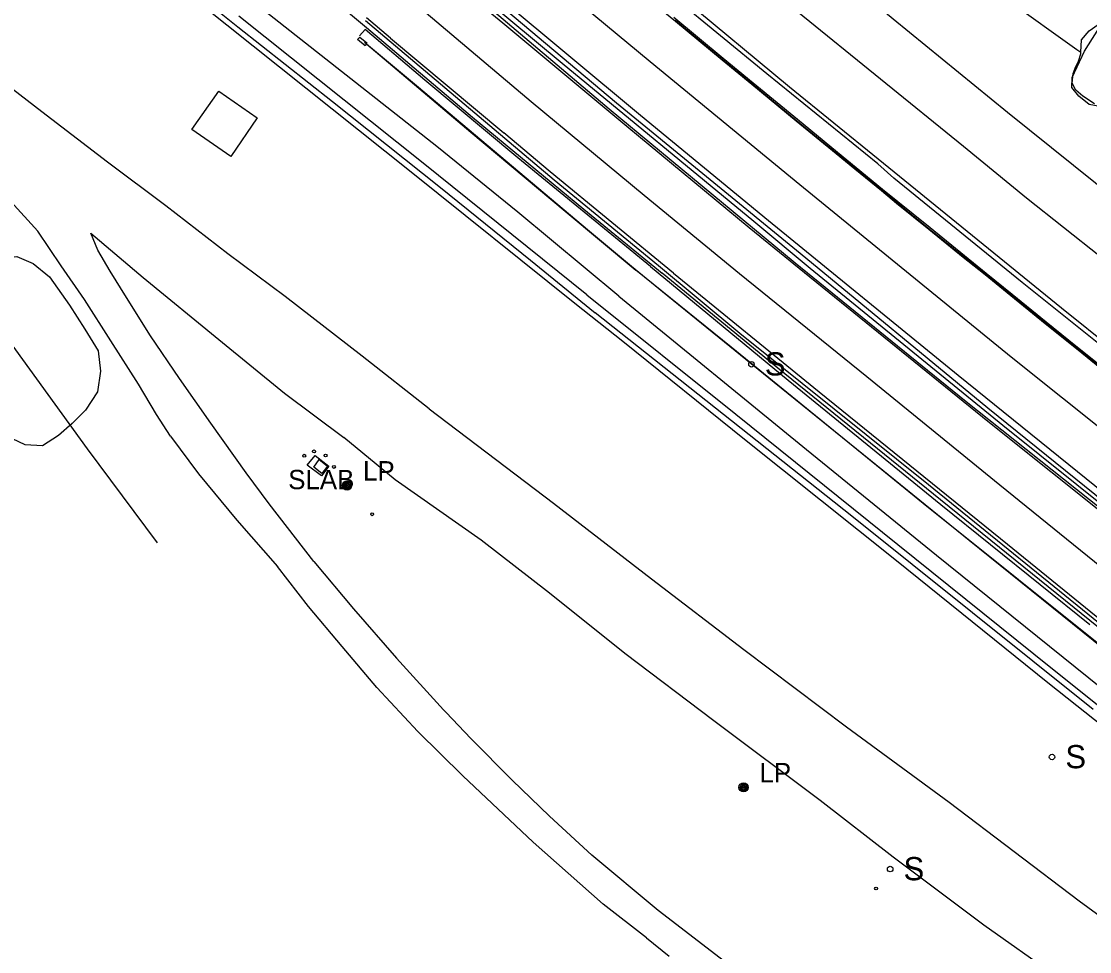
# Model space of a CAD drawing. Extents: x 368532 to 392481, y 10654822 to 10676899.
# Drawn here: x 379727.7 to 380004, y 10659071.4 to 10659311.8 of the extents above; entities that cross this region are included whole.
import ezdxf

# ---------------------------------------------------------------- set-up
doc = ezdxf.new("R2010")
doc.units = 0
for name, color, linetype in [('p_dtm obscured area', 7, 'Continuous'), ('p_dtm retaining wall', 7, 'Continuous'), ('p_dtm sidewalk', 7, 'Continuous'), ('p_dtm slab', 7, 'Continuous'), ('p_railroad rr control', 7, 'Continuous'), ('p_road - paved curb', 7, 'Continuous'), ('p_road conc barrier', 7, 'Continuous'), ('p_road dirt road', 7, 'Continuous'), ('p_road paint stripe', 7, 'Continuous'), ('p_structure building', 7, 'Continuous'), ('p_structure fence', 7, 'Continuous'), ('p_structure sign', 7, 'Continuous'), ('p_structure unidentified', 7, 'Continuous'), ('p_structure wall', 7, 'Continuous'), ('p_utility general pole', 7, 'Continuous'), ('p_veg woods', 7, 'Continuous')]:
    doc.layers.add(name, color=color, linetype=linetype)

msp = doc.modelspace()

# ---------------------------------------------------------------- linework, layer by layer
at = {"layer": 'p_dtm obscured area'}
msp.add_lwpolyline([(380005.29, 10659290.55), (380002.2, 10659292.5), (380000.46, 10659294.07), (379999.46, 10659295.89), (379999.7, 10659298.41), (380000.25, 10659299.73), (380001.13, 10659301.52), (380001.73, 10659303.48), (380001.72, 10659303.82), (380001.72, 10659303.89), (380001.89, 10659307.03), (380003.9, 10659309.42), (380006.21, 10659311)], dxfattribs=at)
at = {"layer": 'p_dtm retaining wall'}
for p, q in [((379982.87, 10659317.34), (380000.72, 10659304.61)), ((379816.5, 10659306.51), (379830.44, 10659294.8)), ((380000.72, 10659304.61), (380001.72, 10659303.89)), ((379830.44, 10659294.8), (379851.18, 10659277.37)), ((379851.18, 10659277.37), (379874.69, 10659257.62)), ((379874.69, 10659257.62), (379885.52, 10659248.52)), ((379885.52, 10659248.52), (379893.51, 10659242.05)), ((379893.51, 10659242.05), (379922.46, 10659218.6)), ((379922.46, 10659218.6), (379947.37, 10659198.43)), ((379947.37, 10659198.43), (379972.88, 10659177.76)), ((379972.88, 10659177.76), (380010.92, 10659146.96))]:
    msp.add_line(p, q, dxfattribs=at)
at = {"layer": 'p_dtm sidewalk'}
for p, q in [((379920.51, 10659298.28), (379890.66, 10659322.93)), ((379816.67, 10659309.76), (379815.2, 10659308.07)), ((379832.07, 10659296.67), (379816.67, 10659309.76)), ((379949.2, 10659274.99), (379920.51, 10659298.28)), ((379856.11, 10659276.58), (379832.07, 10659296.67)), ((379890.4, 10659248.47), (379856.11, 10659276.58)), ((379953.34, 10659271.29), (379949.2, 10659274.99)), ((379986.54, 10659244.35), (379953.34, 10659271.29)), ((379890.4, 10659248.47), (379926, 10659219.11)), ((380020.43, 10659217.2), (379986.54, 10659244.35)), ((379926, 10659219.11), (379965.55, 10659186.98)), ((379965.55, 10659186.98), (380004.03, 10659155.88))]:
    msp.add_line(p, q, dxfattribs=at)
at = {"layer": 'p_dtm slab'}
for p, q in [((379801.61, 10659197.14), (379803.71, 10659199.65)), ((379803.71, 10659199.65), (379807.29, 10659196.89)), ((379805.36, 10659194.34), (379801.61, 10659197.14)), ((379807.29, 10659196.89), (379805.36, 10659194.34))]:
    msp.add_line(p, q, dxfattribs=at)
at = {"layer": 'p_railroad rr control'}
for points in [[(379569.61, 10659644.13), (379609.83, 10659608.08), (379650.67, 10659571.51), (379694.41, 10659532.52), (379741.58, 10659490.92), (379776.45, 10659460.68), (379817.46, 10659425.32), (379860.06, 10659389.56), (379903.79, 10659353.23), (379953.19, 10659312.49), (379982.8, 10659288.36)], [(379971.34, 10659279.52), (379928.46, 10659314.3), (379890.23, 10659345.82), (379857.28, 10659373.19), (379831.54, 10659394.75), (379804.64, 10659417.62), (379771.87, 10659445.91), (379742.98, 10659470.6), (379703.31, 10659505.21), (379666.94, 10659537.5), (379639.55, 10659561.66), (379602.83, 10659594.67), (379578.33, 10659616.76), (379559.4, 10659633.6)], [(379982.8, 10659288.36), (380016.9, 10659261), (380052.84, 10659232.61), (380085.94, 10659206.26), (380120.72, 10659179.3), (380153.32, 10659154.27), (380191.45, 10659125.29), (380231.37, 10659095.21), (380261.57, 10659072.75), (380294.45, 10659048.57), (380330.85, 10659022.17), (380360.99, 10659000.26)], [(380347.38, 10658976.44), (380320.5, 10658997.04), (380307.32, 10659007.82), (380293.12, 10659020.18), (380275.57, 10659035.91), (380257.07, 10659052.87), (380239.39, 10659068.32), (380225.36, 10659080.48), (380211.07, 10659092.38), (380190.43, 10659108.38), (380160.49, 10659131.03), (380132.22, 10659152.81), (380112.56, 10659167.73), (380088.41, 10659186.61), (380066.31, 10659204.03), (380047.58, 10659218.72), (380026.77, 10659235.12), (380006.83, 10659250.97), (379987.69, 10659266.12), (379971.34, 10659279.52)]]:
    msp.add_lwpolyline(points, dxfattribs=at)
at = {"layer": 'p_road - paved curb'}
for p, q in [((379828.13, 10659335.86), (379881.64, 10659290.75)), ((379879.79, 10659289.19), (379832.82, 10659328.91)), ((379816.7, 10659312.04), (379865.52, 10659270.84)), ((379909.27, 10659302.21), (379896.43, 10659312.84)), ((379909.05, 10659301.94), (379896.78, 10659312.1)), ((379916.76, 10659295.62), (379909.05, 10659301.94)), ((379916.98, 10659295.89), (379909.27, 10659302.21)), ((379928.2, 10659286.17), (379916.76, 10659295.62)), ((379928.42, 10659286.44), (379916.98, 10659295.89)), ((379881.64, 10659290.75), (379929.16, 10659251.92)), ((379927.87, 10659249.32), (379879.79, 10659289.19)), ((379938.56, 10659277.71), (379928.2, 10659286.17)), ((379938.78, 10659277.98), (379928.42, 10659286.44)), ((379943.37, 10659273.74), (379938.56, 10659277.71)), ((379943.59, 10659274.01), (379938.78, 10659277.98)), ((379950.23, 10659268.15), (379943.37, 10659273.74)), ((379950.46, 10659268.42), (379943.59, 10659274.01)), ((379865.52, 10659270.84), (379892.53, 10659248.76)), ((379954.18, 10659264.92), (379950.23, 10659268.15)), ((379954.41, 10659265.19), (379950.46, 10659268.42)), ((379962.53, 10659258.16), (379954.18, 10659264.92)), ((379962.75, 10659258.43), (379954.41, 10659265.19)), ((379971.41, 10659250.96), (379962.53, 10659258.16)), ((379971.63, 10659251.23), (379962.75, 10659258.43)), ((379929.16, 10659251.92), (379977.66, 10659211.92)), ((379977.04, 10659246.42), (379971.41, 10659250.96)), ((379977.27, 10659246.69), (379971.63, 10659251.23)), ((379892.53, 10659248.76), (379913.53, 10659231.25)), ((379971.64, 10659213.83), (379927.87, 10659249.32)), ((379983.7, 10659240.97), (379977.04, 10659246.42)), ((379983.93, 10659241.24), (379977.27, 10659246.69)), ((379992.58, 10659233.8), (379983.7, 10659240.97)), ((379992.8, 10659234.07), (379983.93, 10659241.24)), ((380000.9, 10659227.55), (379992.8, 10659234.07)), ((380000.68, 10659227.28), (379992.58, 10659233.8)), ((379913.53, 10659231.25), (379962.31, 10659192.11)), ((380010.89, 10659219.06), (380000.68, 10659227.28)), ((380011.11, 10659219.33), (380000.9, 10659227.55)), ((380023.61, 10659172.45), (379971.64, 10659213.83)), ((379977.66, 10659211.92), (380025.93, 10659173.01)), ((379962.31, 10659192.11), (380009.44, 10659153.87))]:
    msp.add_line(p, q, dxfattribs=at)
for points in [[(380000.59, 10659227.16), (379992.49, 10659233.68), (379983.61, 10659240.85), (379976.95, 10659246.3), (379971.32, 10659250.84), (379962.44, 10659258.04), (379954.09, 10659264.8), (379950.14, 10659268.03), (379943.27, 10659273.62), (379938.46, 10659277.59), (379928.1, 10659286.05), (379916.66, 10659295.5), (379908.95, 10659301.82), (379896.93, 10659311.78), (379896.93, 10659311.78), (379888.66, 10659318.64)], [(380173.31, 10659088.75), (380166.18, 10659094.46), (380158.38, 10659100.73), (380149.87, 10659107.54), (380139.52, 10659115.87), (380122.6, 10659129.43), (380116.16, 10659134.59), (380109.42, 10659140.03), (380104.58, 10659143.88), (380097.03, 10659149.96), (380092.19, 10659153.84), (380084.69, 10659159.83), (380077.34, 10659165.7), (380071.85, 10659170.15), (380064.49, 10659175.96), (380059.28, 10659180.18), (380053.58, 10659184.67), (380048.2, 10659188.95), (380042.38, 10659193.61), (380037.34, 10659197.65), (380026.17, 10659206.53), (380016.41, 10659214.49), (380010.8, 10659218.94), (380000.59, 10659227.16)]]:
    msp.add_lwpolyline(points, dxfattribs=at)
at = {"layer": 'p_road conc barrier'}
for p, q in [((379781.82, 10659339.53), (379817.01, 10659310.29)), ((379867.58, 10659300.98), (379827.67, 10659334.33)), ((379887.43, 10659327.32), (379926.4, 10659294.96)), ((379817.01, 10659310.29), (379844.41, 10659287.12)), ((379917.2, 10659260.08), (379867.58, 10659300.98)), ((379926.4, 10659294.96), (379949.33, 10659276.27)), ((379844.41, 10659287.12), (379873.18, 10659263.31)), ((379949.33, 10659276.27), (379996.75, 10659237.79)), ((379873.18, 10659263.31), (379893.44, 10659246.77)), ((379931.73, 10659247.97), (379917.2, 10659260.08)), ((379981.51, 10659207.38), (379931.73, 10659247.97)), ((379923.36, 10659222.19), (379893.44, 10659246.77)), ((379996.75, 10659237.79), (380043.04, 10659200.37)), ((379965.42, 10659188.13), (379923.36, 10659222.19)), ((380030.82, 10659167.77), (379981.51, 10659207.38)), ((380006.33, 10659155.19), (379965.42, 10659188.13))]:
    msp.add_line(p, q, dxfattribs=at)
at = {"layer": 'p_road dirt road'}
for p, q in [((379733.04, 10659288.45), (379717.81, 10659300.11)), ((379749.98, 10659275.48), (379733.04, 10659288.45)), ((379765.12, 10659264.18), (379749.98, 10659275.48)), ((379731.98, 10659257.6), (379724.99, 10659265.27)), ((379781.13, 10659251.71), (379765.12, 10659264.18)), ((379738.02, 10659248.66), (379731.98, 10659257.6)), ((379747.52, 10659252.72), (379745.69, 10659257.05)), ((379745.69, 10659257.05), (379759.2, 10659245.65)), ((379750.71, 10659247.27), (379747.52, 10659252.72)), ((379795.98, 10659240.76), (379781.13, 10659251.71)), ((379744.04, 10659239.94), (379738.02, 10659248.66)), ((379754.91, 10659240.48), (379750.71, 10659247.27)), ((379759.2, 10659245.65), (379778.84, 10659229.57)), ((379750.84, 10659229.27), (379744.04, 10659239.94)), ((379761.17, 10659230.51), (379754.91, 10659240.48)), ((379815.9, 10659225.26), (379795.98, 10659240.76)), ((379758, 10659218.06), (379750.84, 10659229.27)), ((379768.66, 10659219.56), (379761.17, 10659230.51)), ((379778.84, 10659229.57), (379795.79, 10659215.73)), ((379833.17, 10659211.68), (379815.9, 10659225.26)), ((379762.71, 10659210.21), (379758, 10659218.06)), ((379776.7, 10659207.95), (379768.66, 10659219.56)), ((379795.79, 10659215.73), (379811.14, 10659204.23)), ((379766.35, 10659204.6), (379762.71, 10659210.21)), ((379833.17, 10659211.68), (379865.37, 10659187.26)), ((379785.85, 10659195.17), (379776.7, 10659207.95)), ((379766.35, 10659204.6), (379773.51, 10659194.85)), ((379824.43, 10659193.35), (379811.14, 10659204.23)), ((379773.51, 10659194.85), (379783.43, 10659182.86)), ((379791.83, 10659187.16), (379785.85, 10659195.17)), ((379846.67, 10659177.73), (379824.43, 10659193.35)), ((379803.39, 10659172.2), (379791.83, 10659187.16)), ((379865.37, 10659187.26), (379890.68, 10659167.7)), ((379783.43, 10659182.86), (379793.96, 10659170.89)), ((379864.31, 10659164.02), (379846.67, 10659177.73)), ((379801.97, 10659160.57), (379793.96, 10659170.89)), ((379803.39, 10659172.2), (379813.65, 10659159.94)), ((379890.68, 10659167.7), (379914.55, 10659149.44)), ((379883.81, 10659148.39), (379864.31, 10659164.02)), ((379810.67, 10659150.24), (379801.97, 10659160.57)), ((379813.65, 10659159.94), (379824.75, 10659147.25)), ((379819.65, 10659139.61), (379810.67, 10659150.24)), ((379914.55, 10659149.44), (379941.15, 10659129.51)), ((379824.75, 10659147.25), (379836.93, 10659133.88)), ((379906.83, 10659131.06), (379883.81, 10659148.39)), ((379830.24, 10659128.3), (379819.65, 10659139.61)), ((379836.93, 10659133.88), (379837.59, 10659133.21)), ((379843.96, 10659126.43), (379837.59, 10659133.21)), ((379934.32, 10659110.4), (379906.83, 10659131.06)), ((379941.15, 10659129.51), (379967.7, 10659110.02)), ((379841.94, 10659116.83), (379830.24, 10659128.3)), ((379854.65, 10659115.64), (379843.96, 10659126.43)), ((379860.12, 10659099.61), (379841.94, 10659116.83)), ((379864.33, 10659106.39), (379854.65, 10659115.64)), ((379953.16, 10659095.75), (379934.32, 10659110.4)), ((379967.7, 10659110.02), (380001.32, 10659084.48)), ((379875.24, 10659096.33), (379864.33, 10659106.39)), ((379878.2, 10659083.63), (379860.12, 10659099.61)), ((379892.44, 10659082.01), (379875.24, 10659096.33)), ((379976.61, 10659078.18), (379953.16, 10659095.75)), ((379889.43, 10659074.93), (379878.2, 10659083.63)), ((380001.32, 10659084.48), (380032.48, 10659061.46)), ((379911.85, 10659067.11), (379892.44, 10659082.01)), ((380003.97, 10659058.94), (379976.61, 10659078.18)), ((379889.43, 10659074.93), (379895.24, 10659070.17))]:
    msp.add_line(p, q, dxfattribs=at)
at = {"layer": 'p_road paint stripe'}
for p, q in [((379852.27, 10659311.35), (379822.3, 10659336.16)), ((379840.92, 10659326.67), (379887.85, 10659287.61)), ((379890.36, 10659301.39), (379858.37, 10659327.97)), ((379831.31, 10659314.97), (379859.56, 10659291.11)), ((379823.23, 10659307.51), (379816.99, 10659312.75)), ((379884.28, 10659284.63), (379852.27, 10659311.35)), ((379823.23, 10659307.51), (379852.48, 10659283.04)), ((379929.05, 10659269.59), (379890.36, 10659301.39)), ((379859.56, 10659291.11), (379888.82, 10659266.92)), ((379887.85, 10659287.61), (379920.98, 10659260.34)), ((379915.96, 10659258.44), (379884.28, 10659284.63)), ((379864.51, 10659272.98), (379852.48, 10659283.04)), ((379896.42, 10659246.73), (379864.51, 10659272.98)), ((379951.97, 10659250.85), (379929.05, 10659269.59)), ((379888.82, 10659266.92), (379913.43, 10659246.67)), ((379920.98, 10659260.34), (379970, 10659220.34)), ((379930.22, 10659246.86), (379915.96, 10659258.44)), ((379983.71, 10659225.04), (379951.97, 10659250.85)), ((379896.42, 10659246.73), (379934.02, 10659216.05)), ((379913.43, 10659246.67), (379946.41, 10659220)), ((379977.66, 10659208.42), (379930.22, 10659246.86)), ((380015.31, 10659199.72), (379983.71, 10659225.04)), ((379970, 10659220.34), (380025.41, 10659175.69)), ((379946.41, 10659220), (379980.81, 10659192.06)), ((379934.02, 10659216.05), (379982.72, 10659176.7)), ((380026.29, 10659169.55), (379977.66, 10659208.42)), ((379980.81, 10659192.06), (380011.74, 10659166.95)), ((379982.72, 10659176.7), (380030.53, 10659137.8))]:
    msp.add_line(p, q, dxfattribs=at)
at = {"layer": 'p_structure building'}
msp.add_lwpolyline([(379788.69, 10659286.87), (379781.88, 10659276.91), (379771.8, 10659283.92), (379778.84, 10659293.78)], close=True, dxfattribs=at)
at = {"layer": 'p_structure fence'}
for p, q in [((379762.29, 10659327.71), (379783.7, 10659310.42)), ((379800.02, 10659307.13), (379773.7, 10659327.95)), ((379783.7, 10659310.42), (379808.23, 10659291.1)), ((379835.17, 10659279.51), (379800.02, 10659307.13)), ((379817.1, 10659305.94), (379843.96, 10659283.22)), ((379808.23, 10659291.1), (379836.14, 10659268.86)), ((379843.96, 10659283.22), (379868.35, 10659262.77)), ((379856.1, 10659262.48), (379835.17, 10659279.51)), ((379836.14, 10659268.86), (379859.4, 10659250.08)), ((379882.22, 10659240.83), (379856.1, 10659262.48)), ((379868.35, 10659262.77), (379886.68, 10659247.49)), ((379744.85, 10659201.32), (379709.43, 10659250.22)), ((379859.4, 10659250.08), (379876.16, 10659236.5)), ((379911.29, 10659227.59), (379886.68, 10659247.49)), ((379882.22, 10659240.83), (379930.79, 10659201.16)), ((379942.51, 10659183.89), (379876.16, 10659236.5)), ((379960.94, 10659187.23), (379911.29, 10659227.59)), ((379762.91, 10659177.07), (379744.85, 10659201.32)), ((379930.79, 10659201.16), (379964.43, 10659173.85)), ((380010.28, 10659147.65), (379960.94, 10659187.23)), ((380004.92, 10659133.95), (379942.51, 10659183.89)), ((379964.43, 10659173.85), (380006.92, 10659139.66))]:
    msp.add_line(p, q, dxfattribs=at)
at = {"layer": 'p_structure sign'}
for centre in [(379916.54, 10659223.2), (379994.27, 10659121.66), (379952.41, 10659092.7)]:
    msp.add_circle(centre, 0.713, dxfattribs=at)
at = {"layer": 'p_structure unidentified'}
for p, q in [((379814.63, 10659307.13), (379815.26, 10659307.8)), ((379816.62, 10659305.48), (379814.63, 10659307.13)), ((379815.26, 10659307.8), (379817.1, 10659306.3)), ((379817.1, 10659306.3), (379816.62, 10659305.48)), ((379803.35, 10659196.6), (379804.76, 10659198.55)), ((379804.76, 10659198.55), (379806.89, 10659196.85)), ((379805.47, 10659194.96), (379803.35, 10659196.6)), ((379806.89, 10659196.85), (379805.47, 10659194.96))]:
    msp.add_line(p, q, dxfattribs=at)
for centre in [(379803.42, 10659200.68), (379800.91, 10659199.55), (379806.42, 10659199.62), (379808.58, 10659196.67), (379818.45, 10659184.42), (379948.77, 10659087.66)]:
    msp.add_circle(centre, 0.375, dxfattribs=at)
at = {"layer": 'p_structure wall'}
for p, q in [((379780.91, 10659310.9), (379747.35, 10659337.78)), ((379831.68, 10659275.21), (379784.01, 10659313.21)), ((379828.58, 10659272.89), (379780.91, 10659310.9)), ((379870.84, 10659238.88), (379828.58, 10659272.89)), ((379873.94, 10659241.19), (379831.68, 10659275.21)), ((379873.94, 10659241.19), (379912.53, 10659210.28)), ((379883.28, 10659229.1), (379870.84, 10659238.88)), ((379914.72, 10659203.76), (379883.28, 10659229.1)), ((379912.53, 10659210.28), (379954.37, 10659176.59)), ((379954.06, 10659172.39), (379914.72, 10659203.76)), ((379954.37, 10659176.59), (379993.99, 10659144.78)), ((379993.23, 10659140.86), (379954.06, 10659172.39)), ((379993.99, 10659144.78), (380036.8, 10659110.54)), ((380028.31, 10659112.81), (379993.23, 10659140.86))]:
    msp.add_line(p, q, dxfattribs=at)
at = {"layer": 'p_utility general pole'}
for centre, radius in [((379811.97, 10659191.86), 1.19), ((379811.97, 10659191.86), 0.901), ((379811.97, 10659191.86), 0.608), ((379811.97, 10659191.86), 0.337), ((379811.97, 10659191.86), 0.12), ((379914.5, 10659113.82), 1.19), ((379914.5, 10659113.82), 0.901), ((379914.5, 10659113.82), 0.608), ((379914.5, 10659113.82), 0.337), ((379914.5, 10659113.82), 0.12)]:
    msp.add_circle(centre, radius, dxfattribs=at)
at = {"layer": 'p_veg woods'}
msp.add_lwpolyline([(380008.86, 10659289.43), (380003.88, 10659290.37), (380001.17, 10659292.52), (379999.37, 10659294.74), (379999.47, 10659297.33), (380002.7, 10659304.12), (380007.4, 10659311.65)], dxfattribs=at)
msp.add_lwpolyline([(379713.25, 10659244.74), (379717.01, 10659247.69), (379721.2, 10659250.41), (379726.53, 10659251.03), (379730.76, 10659249.25), (379735.02, 10659245.8), (379740.22, 10659238.44), (379744.16, 10659232.28), (379747.56, 10659226.65), (379748.19, 10659221.43), (379747.41, 10659216.1), (379744.36, 10659211.37), (379740.91, 10659207.86), (379737.35, 10659204.81), (379733.24, 10659202.07), (379728.73, 10659202.39), (379725.43, 10659203.89), (379721.66, 10659204.13), (379716.91, 10659205.23), (379713.34, 10659208.43), (379711.42, 10659212.73), (379711.38, 10659219.42), (379712.51, 10659227.48), (379711.69, 10659241.08)], close=True, dxfattribs=at)

# ---------------------------------------------------------------- texts
at = {"layer": 'p_dtm slab'}
msp.add_text(' SLAB', height=5, dxfattribs=at).set_placement((379794.89, 10659190.9))
at = {"layer": 'p_structure sign'}
for p in [(379920, 10659220.3), (379997.73, 10659118.76), (379955.87, 10659089.8)]:
    msp.add_text('S', height=6, dxfattribs=at).set_placement(p)
at = {"layer": 'p_utility general pole'}
for p in [(379816.09, 10659193.15), (379918.62, 10659115.12)]:
    msp.add_text('LP', height=5, dxfattribs=at).set_placement(p)

doc.saveas('drawing.dxf')
